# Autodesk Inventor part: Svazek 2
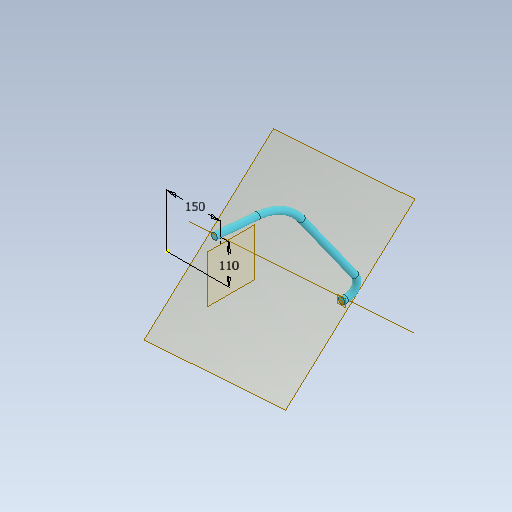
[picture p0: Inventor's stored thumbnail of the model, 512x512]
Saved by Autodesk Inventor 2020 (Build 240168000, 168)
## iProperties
Created: 2025-04
Part Number: Svazek 2
Material: Polyetylen, S vysokou hustotou
Document SubType Name: Modeling
Designer: doma
Density: 0.952 g/cm^3
Appearance: Kadetská modrá
Author: doma
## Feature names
1. Tažení1
## Parameters: d6 = 90 deg, d8 = 18 mm, d9 = 0, d10 = 0
